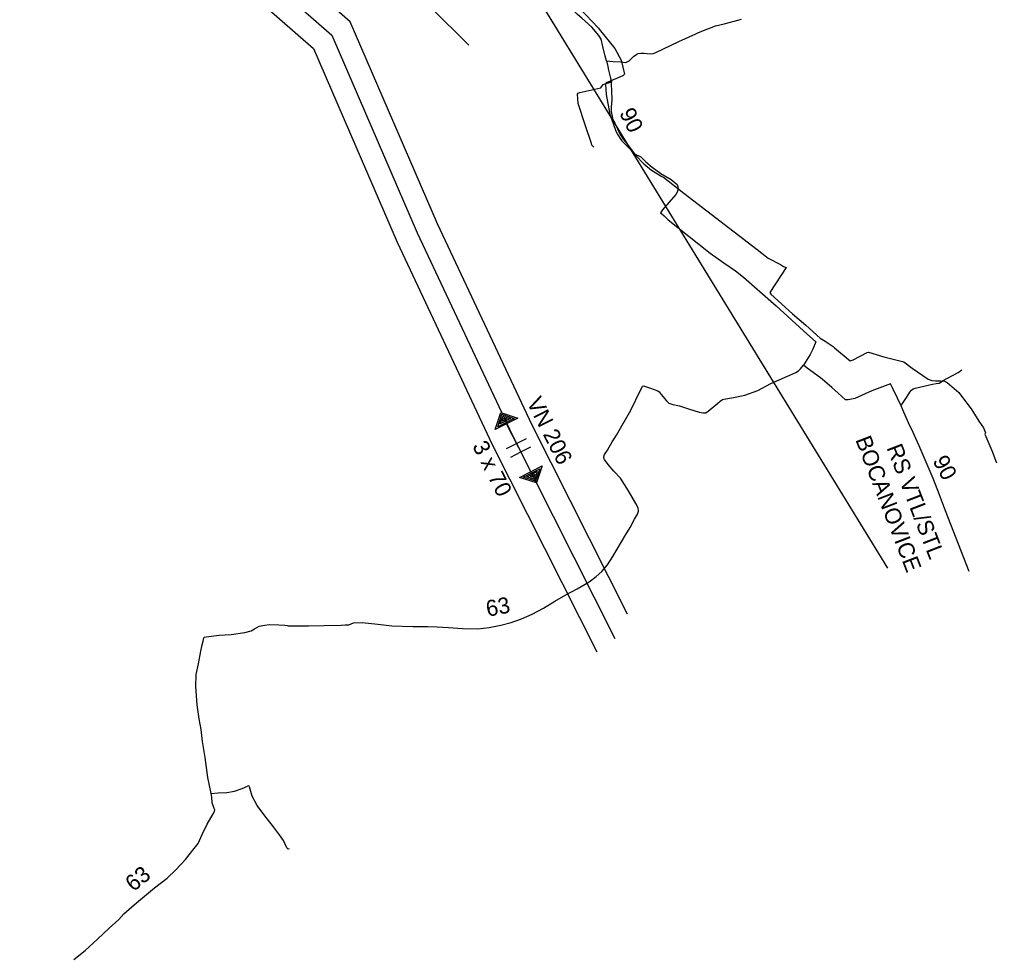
# Model space of a CAD drawing. Extents: x -444841 to -429545, y -1135312 to -1129851.
# Drawn here: x -441649.5 to -441164.6, y -1132367.9 to -1131902.2 of the extents above; entities that cross this region are included whole.
import ezdxf

# ---------------------------------------------------------------- set-up
doc = ezdxf.new("R2010")
doc.units = 0
for name, color, linetype in [('Vrstva 10', 7, 'Continuous'), ('Vrstva 13', 7, 'Continuous'), ('Vrstva 15', 7, 'Continuous'), ('Vrstva 27', 7, 'Continuous'), ('Vrstva 29', 7, 'Continuous'), ('Vrstva 30', 7, 'Continuous'), ('Vrstva 35', 7, 'Continuous'), ('Vrstva 58', 7, 'Continuous'), ('Vrstva 59', 7, 'Continuous')]:
    doc.layers.add(name, color=color, linetype=linetype)

msp = doc.modelspace()

# ---------------------------------------------------------------- linework, layer by layer
at = {"layer": 'Vrstva 10'}
for p, q in [((-441407.8, -1132115.22), (-441402.8, -1132112.7)), ((-441402.8, -1132112.7), (-441397.8, -1132110.18)), ((-441405.66, -1132119.47), (-441400.66, -1132116.95)), ((-441400.66, -1132116.95), (-441395.66, -1132114.43))]:
    msp.add_line(p, q, dxfattribs=at)
for points in [[(-441640.89, -1131756.15), (-441574.87, -1131839.72), (-441494.51, -1131910), (-441452.12, -1132008.18), (-441404.98, -1132108.37), (-441353.98, -1132209.5)], [(-441395.74, -1132126.7), (-441401.73, -1132114.82), (-441407.72, -1132102.95)]]:
    msp.add_lwpolyline(points, dxfattribs=at)
for points in [[(-441413.34, -1132105.78), (-441410.55, -1132097.32), (-441402.09, -1132100.11)], [(-441412.15, -1132104.4), (-441410.11, -1132098.21), (-441403.92, -1132100.25)], [(-441410.96, -1132103.01), (-441409.66, -1132099.09), (-441405.74, -1132100.38)], [(-441409.76, -1132101.63), (-441409.22, -1132099.98), (-441407.56, -1132100.52)], [(-441401.36, -1132129.54), (-441390.11, -1132123.86), (-441392.9, -1132132.32)], [(-441399.54, -1132129.4), (-441391.31, -1132125.25), (-441393.35, -1132131.44)], [(-441397.72, -1132129.26), (-441392.5, -1132126.63), (-441393.79, -1132130.56)], [(-441395.89, -1132129.13), (-441393.7, -1132128.02), (-441394.24, -1132129.67)]]:
    msp.add_lwpolyline(points, close=True, dxfattribs=at)
at = {"layer": 'Vrstva 15'}
for points in [[(-441347.71, -1132197.5), (-441395.09, -1132103.55), (-441442.09, -1132003.66), (-441485.39, -1131903.36), (-441566.87, -1131832.11), (-441625.25, -1131758.2)], [(-441649.52, -1131762.97), (-441582.87, -1131847.33), (-441503.62, -1131916.64), (-441462.15, -1132012.71), (-441414.87, -1132113.19), (-441362.91, -1132216.23)]]:
    msp.add_lwpolyline(points, dxfattribs=at)
at = {"layer": 'Vrstva 27'}
for points in [[(-441358.13, -1131922.69), (-441358.79, -1131920.35), (-441359.9, -1131915.58), (-441360.88, -1131912.03), (-441361.98, -1131910.11), (-441365.48, -1131906.04), (-441370.4, -1131901.57), (-441372.5, -1131899.8), (-441378.42, -1131894.03), (-441380.23, -1131891.81), (-441389.51, -1131881.32), (-441391.67, -1131878.48), (-441392.57, -1131877.6), (-441393.49, -1131876.52), (-441394.31, -1131875.72), (-441396.91, -1131873.09), (-441404.5, -1131865.38), (-441415.65, -1131853.65), (-441428.33, -1131840.06), (-441439.82, -1131827.89), (-441446.05, -1131820.66)], [(-441358.13, -1131922.69), (-441354.92, -1131923.14), (-441351.08, -1131923.27), (-441348.51, -1131923.55), (-441346.86, -1131922.76), (-441344.55, -1131920.44), (-441343.84, -1131919.97), (-441343.07, -1131919.39), (-441342.48, -1131919.12), (-441341.16, -1131918.91), (-441339.46, -1131918.87), (-441336.4, -1131919.34), (-441334.98, -1131919.16), (-441333.61, -1131918.55), (-441322.23, -1131913.07), (-441313.82, -1131909.29), (-441312.44, -1131908.72), (-441307.93, -1131906.86), (-441304, -1131905.38), (-441299.7, -1131904.32), (-441294.74, -1131903.09), (-441291.2, -1131902.06)], [(-441358.13, -1131922.69), (-441357.53, -1131925.58), (-441357.16, -1131927.39), (-441356.14, -1131931.35), (-441355.68, -1131933.13)], [(-441372.17, -1131938.81), (-441371.41, -1131938.44), (-441360.98, -1131936.18), (-441359.86, -1131934.57), (-441355.68, -1131933.13)], [(-441355.68, -1131933.13), (-441355.76, -1131933.81), (-441355.92, -1131934.32), (-441355.64, -1131937.61), (-441355.52, -1131942.17), (-441355.76, -1131945.82), (-441355.79, -1131947.95), (-441354.98, -1131951.96), (-441354.1, -1131953.73), (-441351.35, -1131959.24), (-441349.91, -1131961.59), (-441348.88, -1131962.77), (-441346.74, -1131965.52), (-441344.23, -1131968.84), (-441341.18, -1131970.39), (-441338.66, -1131972.82), (-441335.56, -1131975.54), (-441331.15, -1131978.74), (-441326.09, -1131981.69), (-441323.15, -1131984.2), (-441322.75, -1131985.18), (-441322.59, -1131986.43), (-441323.02, -1131988.01), (-441323.8, -1131989.11), (-441330.4, -1131996.77), (-441331.05, -1131997.7), (-441331.35, -1131998.21), (-441330.72, -1131998.73), (-441329.59, -1131999.7), (-441329.27, -1132000)], [(-441364.45, -1131965.57), (-441365.15, -1131964.99), (-441365.45, -1131964.56), (-441365.64, -1131963.79), (-441368.63, -1131954.97), (-441372.28, -1131943.86), (-441372.47, -1131939.25), (-441372.17, -1131938.81)], [(-441329.27, -1132000), (-441327.5, -1132001.68), (-441306.62, -1132018.15), (-441299.84, -1132023.08), (-441294.15, -1132026.93), (-441290.22, -1132030.08), (-441273.9, -1132044.31), (-441260.29, -1132056.8), (-441254.16, -1132062.27), (-441255.73, -1132065.89), (-441257.09, -1132068.48), (-441260.39, -1132073.78)], [(-441295.08, -1132089.84), (-441289.5, -1132088.74), (-441283.11, -1132086.37), (-441276.65, -1132082.86), (-441264.16, -1132077.52), (-441262.83, -1132076.61), (-441261.84, -1132075.71), (-441260.39, -1132073.78)], [(-441250, -1132081.78), (-441251.91, -1132080.14), (-441258.62, -1132075.27), (-441260.39, -1132073.78)], [(-441211.96, -1132093.97), (-441211.53, -1132093.3), (-441210.48, -1132091.85), (-441208.86, -1132089.35), (-441207.59, -1132087.31), (-441206.78, -1132086.25), (-441205.94, -1132085.54), (-441204.97, -1132085.29), (-441200.59, -1132084.28), (-441196.4, -1132083.28), (-441194.43, -1132082.94), (-441193.06, -1132082.72), (-441192.24, -1132082.34), (-441191.32, -1132081.64), (-441183.6, -1132077.44), (-441181.73, -1132076.13)], [(-441216.04, -1132085.44), (-441217.12, -1132083.03), (-441226.47, -1132086.51), (-441234.89, -1132090.45), (-441238.12, -1132090.98), (-441239.51, -1132091.04), (-441243.14, -1132087.7), (-441246.36, -1132084.92), (-441250, -1132081.78)], [(-441554.47, -1132286.43), (-441556.1, -1132278.5), (-441557.37, -1132268.68), (-441558.74, -1132260.75), (-441559.41, -1132254.77), (-441560.32, -1132249.46), (-441561.35, -1132242.44), (-441561.97, -1132233.44), (-441561.78, -1132227.48), (-441560.73, -1132222.14), (-441559.58, -1132215.91), (-441558.82, -1132212.64), (-441558.3, -1132210.95), (-441557.99, -1132209.23), (-441557.76, -1132208.91), (-441556.84, -1132208.67), (-441550.49, -1132207.95), (-441544.5, -1132207.61), (-441537.7, -1132206.58), (-441534.57, -1132205.74), (-441532.96, -1132204.78), (-441530.59, -1132203.49), (-441527.7, -1132202.86), (-441525.63, -1132202.53), (-441520.78, -1132202.7), (-441517.79, -1132202.91), (-441516.63, -1132203.15), (-441516.13, -1132203.32), (-441515.39, -1132203.33), (-441506.05, -1132203.21), (-441498.28, -1132203.05), (-441489.92, -1132202.9), (-441487.91, -1132202.83), (-441486.06, -1132202.71), (-441483.8, -1132201.84), (-441479.52, -1132201.58), (-441471.65, -1132202.47), (-441464.75, -1132203.19), (-441454.22, -1132203.65), (-441446.86, -1132203.6), (-441442.21, -1132203.83), (-441436.55, -1132204.05), (-441429.62, -1132204.57), (-441422.1, -1132204.68), (-441416.43, -1132204.04), (-441410.55, -1132202.93), (-441405.55, -1132201.64), (-441400.3, -1132199.81), (-441395.07, -1132197.44), (-441389.45, -1132194.48), (-441383.77, -1132191.09), (-441378.28, -1132187.8), (-441372.73, -1132184.92), (-441366.69, -1132181.41), (-441363.24, -1132178.85), (-441360.43, -1132176.23), (-441357.7, -1132173.05), (-441354.95, -1132168.82), (-441350.69, -1132161.58), (-441348.49, -1132157.88), (-441346.42, -1132154.39), (-441344.27, -1132150.26), (-441342.69, -1132147.86), (-441342.32, -1132146.28), (-441342.49, -1132144.67), (-441343.6, -1132142.53), (-441347.16, -1132136.19), (-441351.13, -1132130.02), (-441354.51, -1132126.51), (-441357.31, -1132123.15), (-441359.13, -1132120.61), (-441359.48, -1132119.97), (-441359.54, -1132119.4), (-441359.09, -1132118.27), (-441357.64, -1132115.99), (-441355.26, -1132111.89), (-441353.97, -1132109.84), (-441353.21, -1132108.53), (-441346.14, -1132096.21), (-441341.3, -1132086.26), (-441340.3, -1132084.37), (-441340.01, -1132084.15), (-441339.34, -1132084.26), (-441336.26, -1132085.24), (-441332.71, -1132086.65), (-441332.09, -1132087), (-441331.01, -1132088.36), (-441328.4, -1132091.63), (-441327.26, -1132092.76), (-441325.29, -1132093.3), (-441321.94, -1132093.97), (-441317.52, -1132095.45), (-441312.14, -1132097.17), (-441310.12, -1132097.49), (-441308.8, -1132097.43), (-441307.69, -1132096.61), (-441302.94, -1132092.71), (-441301.75, -1132091.73), (-441300.55, -1132090.87), (-441299.89, -1132090.64), (-441295.08, -1132089.84)], [(-441178.07, -1132176.28), (-441189.93, -1132146.16), (-441192.87, -1132138.22), (-441196.05, -1132130.11), (-441200.02, -1132120.92), (-441202.94, -1132113.92), (-441204.58, -1132110.25), (-441205.94, -1132107.26), (-441208.16, -1132102.55), (-441211.05, -1132096.02), (-441211.96, -1132093.97), (-441213.63, -1132090.27), (-441216.04, -1132085.44)], [(-441554.47, -1132286.43), (-441550.9, -1132286.24), (-441546.54, -1132285.93), (-441542.74, -1132285.28), (-441538.97, -1132284.09), (-441536.29, -1132282.82)], [(-441515.75, -1132314.02), (-441516.15, -1132314.07), (-441516.52, -1132313.88), (-441516.9, -1132313.49), (-441518.42, -1132309.92), (-441520.4, -1132306.99), (-441523.49, -1132303.05), (-441528.25, -1132296.92), (-441531.57, -1132292.48), (-441533.99, -1132287.81), (-441535.3, -1132283.23), (-441535.57, -1132282.8), (-441535.88, -1132282.71), (-441536.29, -1132282.82)], [(-441622.64, -1132368.96), (-441616.93, -1132364.46), (-441610.88, -1132358.8), (-441605.11, -1132353.39), (-441600.3, -1132349.05), (-441597.71, -1132346.29), (-441595.14, -1132343.95), (-441591.52, -1132340.84), (-441582.46, -1132333.42), (-441576.2, -1132328.5), (-441572, -1132324.45), (-441567.12, -1132319.26), (-441563.5, -1132314.6), (-441560.84, -1132311.28), (-441558.84, -1132306.9), (-441556.4, -1132301.71), (-441553.34, -1132296.6), (-441552.67, -1132295.41), (-441552.61, -1132294.7), (-441552.88, -1132293.93), (-441553.84, -1132291.07), (-441554.11, -1132288.4), (-441554.47, -1132286.43)]]:
    msp.add_lwpolyline(points, dxfattribs=at)
at = {"layer": 'Vrstva 35'}
msp.add_lwpolyline([(-441493.03, -1131866.42), (-441476.22, -1131874.15), (-441445.72, -1131895.91), (-441426.48, -1131915.01)], dxfattribs=at)
at = {"layer": 'Vrstva 58'}
for points in [[(-441377.89, -1131889.75), (-441362.06, -1131906.6), (-441361.76, -1131907.03), (-441354.05, -1131916.59), (-441350.84, -1131922.38), (-441349.16, -1131929.28), (-441350.04, -1131930.19), (-441358.27, -1131933.58), (-441358.62, -1131934.44), (-441358.41, -1131936.74), (-441358.24, -1131939.5), (-441356.49, -1131949.24), (-441353.69, -1131957.19), (-441352.86, -1131959.02), (-441350.64, -1131962.3), (-441346.93, -1131966.02), (-441343.79, -1131969.58), (-441339.7, -1131973.9), (-441335.89, -1131976.97), (-441330.71, -1131980.11), (-441329.83, -1131980.51), (-441319.72, -1131988.4), (-441283.43, -1132016.38), (-441277.89, -1132020.72), (-441271.85, -1132023.9), (-441270.35, -1132024.9), (-441269, -1132025.36), (-441277.13, -1132037.83), (-441276.57, -1132038.65), (-441265.76, -1132048.29), (-441259.14, -1132054.04), (-441252.08, -1132060.36), (-441249.69, -1132061.94), (-441245.62, -1132064.49), (-441244.92, -1132065.16), (-441237.19, -1132071.74), (-441235.76, -1132071.22), (-441228.76, -1132067.59), (-441228.17, -1132067.35), (-441220.47, -1132069.64), (-441210.6, -1132072.2), (-441206.39, -1132075.28), (-441198.54, -1132080.74), (-441196.67, -1132081.53), (-441194.87, -1132081.56), (-441192.34, -1132081.66), (-441190.34, -1132081.81), (-441189.04, -1132082.37), (-441183.24, -1132087.41), (-441181.9, -1132089.24)], [(-441181.9, -1132089.24), (-441177.14, -1132095.48), (-441173.39, -1132101.62), (-441170.98, -1132104.91), (-441169.94, -1132107.38), (-441170.29, -1132108.15), (-441166.8, -1132116.22), (-441164.58, -1132122.32)]]:
    msp.add_lwpolyline(points, dxfattribs=at)
at = {"layer": 'Vrstva 59'}
msp.add_lwpolyline([(-441218.58, -1132174.63), (-441459.69, -1131781.27), (-441291.98, -1131581.6)], dxfattribs=at)

# ---------------------------------------------------------------- texts
at = {"layer": 'Vrstva 13'}
for s, p in [('VN 206', (-441397.95, -1132092.17)), ('3 x 70', (-441424.94, -1132113.92))]:
    msp.add_text(s, height=8, rotation=296.7619, dxfattribs=at).set_placement(p)
at = {"layer": 'Vrstva 29'}
for s, p in [('BOCANOVICE', (-441234.72, -1132110.8)), (' RS VTL/STL', (-441220.3, -1132112.05))]:
    msp.add_text(s, height=8, rotation=291.1048, dxfattribs=at).set_placement(p)
at = {"layer": 'Vrstva 30'}
for s, rotation, p in [('90', 296.461, (-441351.97, -1131948.57)), ('90', 298.0894, (-441196.46, -1132121.27)), ('63', 10.6902, (-441417.17, -1132198.79)), ('63', 39.3169, (-441592.94, -1132335.55))]:
    msp.add_text(s, height=8, rotation=rotation, dxfattribs=at).set_placement(p)

doc.saveas('drawing.dxf')
